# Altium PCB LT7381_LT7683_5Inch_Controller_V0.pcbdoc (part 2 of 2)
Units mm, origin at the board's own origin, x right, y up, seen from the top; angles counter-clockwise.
Board outline 60 x 56 mm, 2 copper layers (Top Layer, Bottom Layer); 80 components, 113 nets, 434 pads, 201 vias.
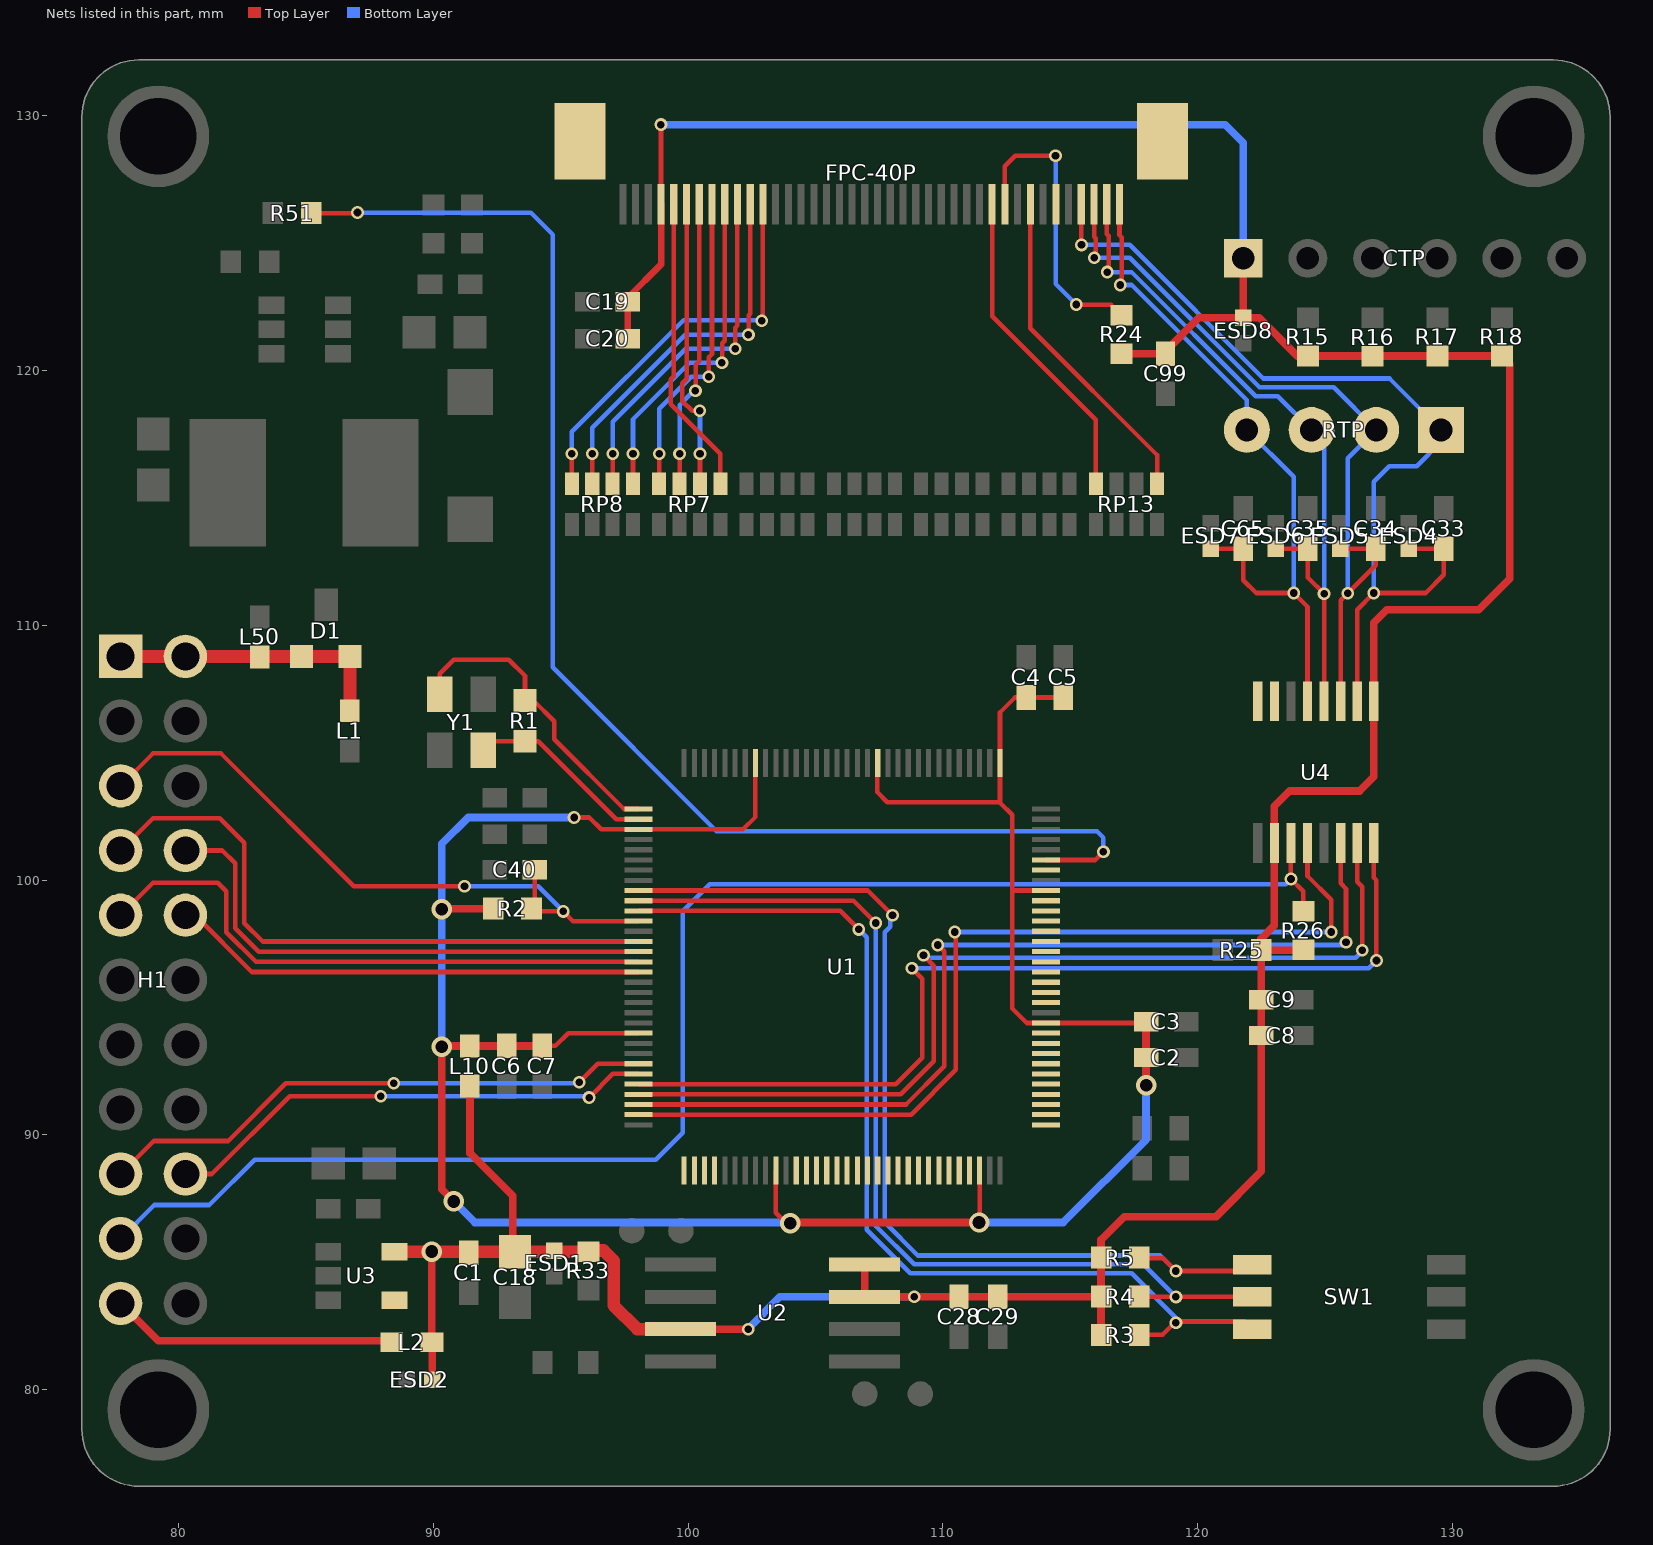
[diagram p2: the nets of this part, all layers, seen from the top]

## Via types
v1: diameter 0.5, hole 0.3, Top Layer to Bottom Layer, 104 vias
v2: diameter 0.8, hole 0.5, Top Layer to Bottom Layer, 97 vias

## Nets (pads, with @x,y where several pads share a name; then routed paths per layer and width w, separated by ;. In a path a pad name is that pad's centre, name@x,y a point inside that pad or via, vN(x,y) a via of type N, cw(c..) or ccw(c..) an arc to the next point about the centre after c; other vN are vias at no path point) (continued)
LT768_DB6_SDI: H1.17 U1.26 | length 22.1
  Top Layer w0.18: H1.17@77.724,88.46 79.02,89.756 81.941,89.756 84.204,92.019 88.441,92.019 v1(88.443,92.017) ; v1(95.725,92.056) 96.457,92.788 U1.26@98.045,92.788
  Bottom Layer w0.18: v1(88.443,92.017) 95.686,92.017 v1(95.725,92.056)
LT768_DB7_SCLK: H1.18 U1.27 | length 19.5
  Top Layer w0.18: H1.18@80.264,88.46 81.305,88.46 84.355,91.509 v1(87.935,91.509) ; v1(96.114,91.458) 97.043,92.388 U1.27@98.045,92.388
  Bottom Layer w0.18: v1(87.935,91.509) 87.937,91.507 96.065,91.507 v1(96.114,91.458)
LT768_INT: U1.36
LT768_PS0: R3.1 SW1.6 U1.11 | length 39.7
  Top Layer w0.18: U1.11@98.045,98.788 105.979,98.788 v1(106.705,98.061) ; R3.1@117.72,82.129 117.747,82.156 118.639,82.156 119.151,82.669 121.844,82.669 SW1.6@122.149,82.364 SW1.6@122.453,82.364
  Bottom Layer w0.18: v1(106.705,98.061) 107.01,97.756 107.01,86.276 108.727,84.559 117.414,84.559 119.151,82.821 v1(119.151,82.618)
LT768_PS1: R4.1 SW1.5 U1.10 | length 39
  Top Layer w0.18: U1.10@98.045,99.188 106.493,99.188 v1(107.366,98.315) ; R4.1@117.721,83.648 117.734,83.634 v1(119.151,83.634) SW1.5@122.149,83.634
  Bottom Layer w0.18: v1(107.366,98.315) 107.366,86.416 108.872,84.909 117.876,84.909 v1(119.151,83.634)
LT768_PS2: R5.1 SW1.4 U1.9 | length 40
  Top Layer w0.18: U1.9@98.045,99.588 107.058,99.588 v1(108.026,98.62) ; R5.1@117.72,85.177 117.741,85.156 118.645,85.156 v1(119.151,84.65) 122.301,84.65 SW1.4@122.555,84.904
  Bottom Layer w0.18: v1(108.026,98.62) 107.938,98.532 107.938,98.166 107.716,97.944 107.716,86.561 109.018,85.26 118.542,85.26 v1(119.151,84.65)
LT768_PWM0: U1.90
LT768_PWM1: R51.1 U1.91 | length 54.2
  Top Layer w0.18: R51.1@85.208,126.179 86.994,126.179 v1(87.02,126.206) ; U1.91@114.045,100.788 115.985,100.788 v1(116.307,101.109)
  Bottom Layer w0.18: v1(87.02,126.206) 93.828,126.206 94.691,125.342 94.691,108.348 101.117,101.922 116.053,101.922 116.307,101.668 v1(116.307,101.109)
LT768_RD#: H1.7 U1.14 | length 24.7
  Top Layer w0.18: H1.7@77.724,101.16 78.994,102.43 81.61,102.43 82.58,101.46 82.58,98.31 83.303,97.588 U1.14@98.045,97.588
LT768_RS/A0: H1.9 U1.16 | length 23.1
  Top Layer w0.18: H1.9@77.724,98.62 78.994,99.89 81.534,99.89 81.87,99.554 81.87,97.954 83.036,96.788 U1.16@98.045,96.788
LT768_RST: C40.1 H1.5 R2.1 U1.12 | length 26.5
  Top Layer w0.18: H1.5@77.724,103.7 78.994,104.97 81.661,104.97 86.875,99.756 v1(91.225,99.756) ; R2.1@93.853,98.874 R2.1@93.958,98.769 ; C40.1@93.98,100.398 93.98,98.791 R2.1@93.958,98.769 ; U1.12@98.045,98.388 95.482,98.388 v1(95.101,98.769) R2.1@93.958,98.769
  Bottom Layer w0.18: v1(91.225,99.756) 94.114,99.756 v1(95.101,98.769)
LT768_VDD3.3V: C2.1 C3.1 C4.1 C5.1 C6.1 C7.1 L10.2 R2.2 U1.3 U1.23 U1.42 U1.62 U1.75 U1.88 U1.97 U1.109 U1.121 | length 104.9
  Top Layer w0.18: C7.1@94.382,93.486 94.789,93.486 95.29,93.988 U1.23@98.045,93.988 ; v1(95.525,102.456) 96.125,102.456 96.593,101.988 U1.3@98.045,101.988 102.157,101.988 102.645,102.476 U1.121@102.645,104.588 ; U1.42@103.445,88.588 103.445,86.945 103.861,86.53 v2(104.013,86.53) ; U1.109@107.445,104.588 107.425,104.568 107.425,103.456 107.825,103.056 112.245,103.056 ; v2@111.445,86.576 U1.62@111.445,88.588 ; U1.88@114.045,99.588 112.73,99.588 112.725,99.583 ; C5.1@114.732,107.166 C4.1@113.278,107.166 112.835,107.166 112.245,106.576 U1.97@112.245,104.588 112.245,103.056 ; C3.1@117.981,94.428 117.94,94.388 U1.75@114.045,94.388 113.293,94.388 112.725,94.956 112.725,99.583 ; 112.245,103.056 112.245,103.036 112.725,102.556 112.725,99.583
  Top Layer w0.3: v2(90.325,98.856) 90.343,98.874 R2.2@92.346,98.874 ; v2@90.925,87.256 90.325,87.856 v2(90.325,93.456) 90.355,93.486 L10.2@91.423,93.486 C6.1@92.883,93.486 C7.1@94.28,93.486 ; v2(104.013,86.53) 104.039,86.556 v2(111.425,86.556) ; v2@117.981,91.956 C2.1@117.981,93.031 C3.1@117.981,94.428
  Bottom Layer w0.3: v2(90.325,93.456) v2(90.325,98.856) 90.325,101.418 91.363,102.456 v1(95.525,102.456) ; v2(90.799,87.382) 91.625,86.556 103.987,86.556 v2(104.013,86.53) ; v2(111.425,86.556) 114.725,86.556 117.981,89.812 v2@117.981,91.956
  other v2: 117.983,91.94
LT768_WAIT: H1.10 U1.17 | length 18.7
  Top Layer w0.18: H1.10@80.264,98.62 80.645,98.62 82.877,96.388 U1.17@98.045,96.388
LT768_WR#: H1.8 U1.15 | length 20.9
  Top Layer w0.18: H1.8@80.264,101.16 81.712,101.16 82.22,100.652 82.22,98.112 83.144,97.188 U1.15@98.045,97.188
LT768_XI: R1.1 U1.1 Y1.3 | length 12.2
  Top Layer w0.18: Y1.3@90.25,107.299 90.25,108.098 90.805,108.653 92.964,108.653 93.597,108.02 R1.1@93.597,107.049 93.933,107.049 94.742,106.24 94.742,105.53 97.484,102.788 U1.1@98.045,102.788
LT768_XO: R1.2 U1.2 Y1.1 | length 7.5
  Top Layer w0.18: Y1.1@91.95,105.099 92.3,105.449 R1.2@93.597,105.449 94.112,105.449 97.173,102.388 U1.2@98.045,102.388
ON/OFF: FPC-40P.31 R24.2 | length 11.2
  Top Layer w0.18: FPC-40P.31@112.438,126.528 112.438,128.026 112.852,128.44 v1(114.427,128.44) ; v1(115.24,122.598) 115.259,122.578 116.611,122.578
  Bottom Layer w0.18: v1(114.427,128.44) 114.427,123.41 v1(115.24,122.598)
PCLK: FPC-40P.30 RP13.8 | length 12.7
  Top Layer w0.18: FPC-40P.30@111.938,126.528 111.938,122.14 116.012,118.066 RP13.8@116.012,115.559
R0: FPC-40P.5 RP7.5 | length 11.8
  Top Layer w0.18: FPC-40P.5@99.438,126.528 99.438,119.777 99.325,119.663 99.325,118.676 101.267,116.734 RP7.5@101.267,115.559
R1: FPC-40P.6 RP7.6 | length 11.4
  Top Layer w0.18: FPC-40P.6@99.938,126.528 99.948,126.519 99.948,119.677 99.778,119.507 99.778,118.803 100.157,118.424 v1(100.457,118.424) ; RP7.6@100.467,115.559 v1@100.467,116.644
  Bottom Layer w0.18: v1(100.457,118.424) 100.467,118.414 v1(100.467,116.733)
  other v1: 100.467,116.733
R2: FPC-40P.7 RP7.7 | length 11.3
  Top Layer w0.18: RP7.7@99.667,115.559 v1(99.667,116.733) ; v1(100.288,119.208) 100.298,119.218 100.298,120.23 100.438,120.37 FPC-40P.7@100.438,126.528
  Bottom Layer w0.18: v1(99.667,116.733) 99.667,118.65 100.225,119.208 v1(100.288,119.208)
R3: FPC-40P.8 RP7.8 | length 12.2
  Top Layer w0.18: RP7.8@98.867,115.559 v1(98.867,116.733) ; v1(100.808,119.758) 100.818,119.768 100.818,120.519 100.938,120.639 FPC-40P.8@100.938,126.528
  Bottom Layer w0.18: v1(98.867,116.733) 98.867,118.508 100.117,119.758 v1(100.808,119.758)
R4: FPC-40P.9 RP8.5 | length 13.2
  Top Layer w0.18: RP8.5@97.838,115.559 v1(97.838,116.733) ; v1(101.328,120.308) 101.338,120.318 101.338,121.069 101.438,121.169 FPC-40P.9@101.438,126.528
  Bottom Layer w0.18: v1(97.838,116.733) 97.838,118.091 100.055,120.308 v1(101.328,120.308)
R5: FPC-40P.10 RP8.6 | length 14.1
  Top Layer w0.18: RP8.6@97.038,115.559 v1(97.038,116.733) ; v1(101.848,120.858) 101.858,120.868 101.858,121.689 101.938,121.769 FPC-40P.10@101.938,126.528
  Bottom Layer w0.18: v1(97.038,116.733) 97.038,117.986 99.91,120.858 v1(101.848,120.858)
R6: FPC-40P.11 RP8.7 | length 15
  Top Layer w0.18: RP8.7@96.238,115.559 v1(96.238,116.733) ; v1(102.368,121.408) 102.378,121.418 102.378,122.169 102.438,122.229 FPC-40P.11@102.438,126.528
  Bottom Layer w0.18: v1(96.238,116.733) 96.238,117.761 99.885,121.408 v1(102.368,121.408)
R7: FPC-40P.12 RP8.8 | length 15.9
  Top Layer w0.18: RP8.8@95.438,115.559 v1(95.438,116.733) ; v1(102.888,121.958) 102.938,122.008 FPC-40P.12@102.938,126.528
  Bottom Layer w0.18: v1(95.438,116.733) 95.438,117.596 99.822,121.98 102.866,121.98 v1(102.888,121.958)
RTP_CS: U1.29 U4.15 | length 38.2
  Top Layer w0.18: U1.29@98.045,91.588 108.357,91.588 109.652,92.883 109.652,96.639 v1(109.245,97.045) ; U4.15@126.269,101.458 126.269,99.935 126.467,99.738 v1(126.467,97.248)
  Bottom Layer w0.18: v1(109.245,97.045) 109.349,96.942 126.211,96.942 126.467,97.198 v1(126.467,97.248)
RTP_DCLK: U1.28 U4.16 | length 38.3
  Top Layer w0.18: U1.28@98.045,91.988 108.157,91.988 109.195,93.026 109.195,96.131 v1(108.788,96.537) ; U4.16@126.919,101.458 126.919,100.098 127.025,99.992 v1(127.025,96.842)
  Bottom Layer w0.18: v1(108.788,96.537) 108.991,96.537 108.993,96.535 126.719,96.535 v1(127.025,96.842)
RTP_DIN: U1.30 U4.14 | length 37.6
  Top Layer w0.18: U1.30@98.045,91.188 108.557,91.188 110.058,92.689 110.058,97.198 v1(109.804,97.452) ; U4.14@125.619,101.458 125.619,99.874 125.832,99.661 v1(125.832,97.554)
  Bottom Layer w0.18: v1(109.804,97.452) 109.806,97.45 125.727,97.45 v1(125.832,97.554)
RTP_INT: H1.19 R26.2 U4.11 | length 59.8
  Top Layer w0.18: U4.11@123.669,101.458 123.658,101.447 123.658,100.057 v1(123.673,100.042) 124.155,99.56 R26.2@124.155,98.769
  Bottom Layer w0.18: H1.19@77.724,85.92 79.045,87.241 81.204,87.241 82.983,89.02 98.731,89.02 99.797,90.086 99.797,98.772 100.858,99.834 123.464,99.834 v1(123.673,100.042)
RTP_SDO: U1.31 U4.12 | length 37.3
  Top Layer w0.18: U1.31@98.045,90.788 108.757,90.788 110.515,92.546 110.515,97.909 v1(110.465,97.96) ; U4.12@124.319,101.458 124.319,100.158 125.247,99.23 v1(125.247,97.96)
  Bottom Layer w0.18: v1(110.465,97.96) v1(125.247,97.96)
VDD_3.3V: C1.1 C8.1 C9.1 C18.1 C19.1 C20.1 C28.1 C29.1 C99.1 CTP.1 ESD1.1 ESD2.1 ESD8.1 FPC-40P.4 L2.1 L10.1 R3.2 R4.2 R5.2 R15.1 R16.1 R17.1 R18.1 R24.1 R25.2 R26.1 R33.2 U2.3 U2.7 U2.8 U3.5 U4.1 U4.10 | length 154.2
  Top Layer w0.18: v1(98.933,129.659) 98.938,129.653 FPC-40P.4@98.938,126.528 ; v1(102.357,82.369) v1@102.362,82.364 ; R26.1@124.138,97.245 R26.1@124.155,97.262
  Top Layer w0.2: L2.1@89.941,81.857 L2.1@89.951,81.848
  Top Layer w0.254: C20.1@97.625,121.251 C19.1@97.625,122.701 ; C19.1@97.627,122.701 97.627,122.858 98.938,124.169 FPC-40P.4@98.938,126.528
  Top Layer w0.3: L2.1@89.941,81.857 v2@89.941,85.41 ; ESD2.1@89.951,80.384 L2.1@89.951,81.848 ; L10.1@91.44,91.997 91.44,89.274 93.116,87.598 C18.1@93.116,85.41 ; 92.38,85.336 92.38,85.41 ; 92.55,85.41 92.804,85.41 C18.1@92.885,85.491 ; U2.3@99.707,82.369 v1(102.357,82.369) ; U2.8@106.93,84.909 U2.7@106.93,83.639 106.933,83.636 v1(108.882,83.636) C28.1@110.637,83.636 C29.1@112.161,83.636 116.203,83.636 R4.2@116.214,83.647 ; R3.2@116.214,82.129 R4.2@116.214,83.647 ; R24.1@117.018,120.665 118.74,120.665 C99.1@118.744,120.669 118.744,120.768 120.05,122.074 ESD8.1@121.793,122.074 ; CTP.1@121.793,124.401 ESD8.1@121.793,122.074 ; R26.1@124.138,97.245 R25.2@122.496,97.245 ; R4.2@116.214,83.648 R5.2@116.214,85.177 116.214,85.878 117.119,86.784 120.726,86.784 122.504,88.562 C8.1@122.504,93.896 C9.1@122.504,95.293 122.504,97.236 R25.2@122.496,97.245 ; ESD8.1@121.793,122.074 122.419,122.074 123.918,120.574 R15.1@124.333,120.574 R17.1@129.413,120.574 R18.1@131.953,120.574 132.258,120.269 132.258,111.828 131.039,110.609 127.432,110.609 126.919,110.096 U4.1@126.919,107.018 126.924,107.014 126.924,104.056 126.365,103.497 123.622,103.497 123.019,102.894 U4.10@123.019,101.458 123.019,98.217 122.496,97.693 R25.2@122.496,97.245
  Top Layer w0.5: U3.5@88.475,85.41 89.941,85.41 92.38,85.41 92.55,85.41 ; C18.1@92.804,85.41 93.116,85.41 95.988,85.41 96.034,85.456 96.68,85.456 97.079,85.058 97.079,83.302 98.012,82.369 U2.3@99.707,82.369
  Bottom Layer w0.3: v1(98.933,129.659) 121.082,129.659 121.793,128.948 CTP.1@121.793,124.401 ; v1(102.357,82.369) 102.357,82.385 103.607,83.634 108.88,83.634 v1(108.882,83.636)
  other v2: 89.941,85.412
VDD_3.3V_O: H1.21 L2.2 | length 11.3
  Top Layer w0.3: H1.21@77.724,83.38 79.196,81.908 88.316,81.908 L2.2@88.367,81.857
VIN: D1.1 D1.2 H1.1 H1.2 L1.1 L50.1 | length 11.1
  Top Layer w0.5: H1.1@77.724,108.78 H1.2@80.264,108.78 84.826,108.78 D1.2@86.73,108.78 ; L1.1@86.716,106.648 86.731,106.663 D1.2@86.731,108.779
VSYNC: FPC-40P.33 RP13.5 | length 13
  Top Layer w0.18: FPC-40P.33@113.438,126.528 113.438,121.66 118.412,116.686 RP13.5@118.412,115.559
X+: C33.1 ESD4.1 FPC-40P.37 RTP.1 U4.2 | length 36.8
  Top Layer w0.18: FPC-40P.37@115.438,126.528 115.438,124.939 v1(115.443,124.934) ; U4.2@126.269,107.018 126.269,110.615 v1(126.924,111.269) 128.956,111.269 129.667,111.98 129.667,113.009 C33.1@129.67,113.012 ESD4.1@128.295,113.012
  Bottom Layer w0.18: v1(115.443,124.934) 115.445,124.936 117.335,124.936 122.579,119.692 127.537,119.692 RTP.1@129.558,117.67 129.558,117.206 128.6,116.248 127.533,116.248 126.924,115.638 v1(126.924,111.269)
X-: C35.1 ESD6.1 FPC-40P.39 RTP.3 U4.4 | length 27.5
  Top Layer w0.18: FPC-40P.39@116.438,126.528 116.438,125.361 116.51,125.29 116.51,123.918 v1(116.459,123.868) ; ESD6.1@123.065,113.012 C35.1@124.336,113.012 124.333,113.009 124.333,111.879 v1(124.969,111.242) U4.4@124.969,107.018
  Bottom Layer w0.18: v1(116.459,123.868) 116.461,123.87 117.41,123.87 122.289,118.991 123.158,118.991 RTP.3@124.478,117.67 124.969,117.179 v1(124.969,111.242)
Y+: C34.1 ESD5.1 FPC-40P.38 RTP.2 U4.3 | length 30.9
  Top Layer w0.18: FPC-40P.38@115.938,126.528 115.938,125.252 116.002,125.188 116.002,124.477 v1(115.951,124.426) ; ESD5.1@125.605,113.012 C34.1@127.003,113.012 127.003,112.364 v1(125.902,111.263) 125.619,110.981 U4.3@125.619,107.018
  Bottom Layer w0.18: v1(115.951,124.426) 115.953,124.428 117.347,124.428 122.434,119.341 125.347,119.341 RTP.2@127.018,117.67 125.902,116.554 v1(125.902,111.263)
Y-: C65.1 ESD7.1 FPC-40P.40 RTP.4 U4.5 | length 27.6
  Top Layer w0.18: FPC-40P.40@116.938,126.528 116.938,125.319 117.018,125.239 117.018,123.41 v1(116.967,123.36) ; ESD7.1@120.525,113.012 C65.1@121.796,113.012 121.796,112.426 121.793,112.424 121.793,111.777 122.301,111.269 v1(123.774,111.269) 124.319,110.724 U4.5@124.319,107.018
  Bottom Layer w0.18: v1(116.967,123.36) 117.424,123.36 121.938,118.846 RTP.4@121.938,117.67 123.774,115.834 v1(123.774,111.269)
"": FPC-40P.35 FPC-40P.41 FPC-40P.42 U1.33 U1.34 U1.35 U1.44 U1.45 U1.46 U1.47 U1.48 U1.49 U1.50 U1.51 U1.52 U1.53 U1.54 U1.55 U1.56 U1.57 U1.58 U1.59 U1.60 U1.61 U1.65 U1.66 U1.67 U1.68 U1.69 U1.70 U1.71 U1.72 U1.73 U1.74 U1.77 U1.78 U1.79 U1.80 U1.81 U1.82 U1.83 U1.84 U1.85 U1.86 U1.87 U3.4 U4.7 U4.8

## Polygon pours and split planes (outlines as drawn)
GND on Bottom Layer (solid, remove dead copper, pour order 0): 76.2,76.2 76.2,111.982 92.507,111.982 93.777,113.252 93.777,132.2 136.2,132.2 136.2,76.2
GND on Bottom Layer (solid, remove dead copper, pour order 1): 76.2,112.286 92.354,112.286 93.472,113.404 93.472,132.2 76.2,132.2
GND on Top Layer (solid, remove dead copper, pour order 2): 76.2,76.2 76.2,111.982 92.507,111.982 93.777,113.252 93.777,132.2 136.2,132.2 136.2,76.2
GND on Top Layer (solid, remove dead copper, pour order 3): 76.2,112.286 92.354,112.286 93.472,113.404 93.472,132.2 76.2,132.2

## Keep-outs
Board Outline Layer:
  the board outline again, w0.254

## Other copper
Top Layer:
  drawing of 449 lines, arcs and shapes, not listed
Bottom Layer:
  region net Y-: 122.171,116.801 122.766,116.716 122.893,116.843 122.808,117.437
  region net Y-: 122.388,118.45 122.028,118.846 121.848,118.846 121.488,118.45
  region net X-: 124.526,116.772 124.879,116.428 125.059,116.545 125.281,117.263
  region net X-: 124.245,118.54 123.651,118.625 123.524,118.498 123.609,117.903
  region net Y+: 126.149,117.437 126.064,116.843 126.191,116.716 126.785,116.801
  region net Y+: 126.785,118.54 126.191,118.625 126.064,118.498 126.149,117.903
  region net X+: 128.563,118.539 128.658,118.252 128.976,118.57 128.69,118.666
  region net X+: 128.9,116.675 129.155,116.675 129.441,116.77 128.805,116.77
  region net RTP_INT: 78.545,86.14 78.629,86.698 78.502,86.825 77.944,86.741
  region net CTP_INT: 81.104,85.792 81.354,86.4 81.283,86.583 80.795,86.584
  region net FLASH_SPI_SO: 101.817,83.509 101.95,83.544 101.95,83.724 101.817,83.759
  region net FLASH_SPI_SCLK: 103.976,82.239 104.109,82.274 104.109,82.454 103.976,82.489
  region net FLASH_SPI_SCLK: 104.812,82.489 104.679,82.454 104.679,82.274 104.812,82.239
  region net FLASH_SPI_SO: 103.137,84.331 103.067,84.212 103.194,84.085 103.313,84.155
  region net LT768_RST: 95.036,99.01 94.917,99.08 94.79,98.953 94.86,98.834
  region net LT768_RST: 91.442,99.631 91.575,99.666 91.575,99.846 91.442,99.881
  region net R6: 96.363,116.95 96.328,117.083 96.148,117.083 96.113,116.95
  region net R5: 97.163,116.95 97.128,117.083 96.948,117.083 96.913,116.95
  region net R4: 97.963,116.95 97.928,117.083 97.748,117.083 97.713,116.95
  region net R3: 98.992,116.95 98.957,117.083 98.777,117.083 98.742,116.95
  region net R2: 99.792,116.95 99.757,117.083 99.577,117.083 99.542,116.95
  region net R7: 95.563,116.95 95.528,117.083 95.348,117.083 95.313,116.95
  region net R7: 102.684,122.102 102.547,122.07 102.531,121.89 102.662,121.853
  region net R6: 102.152,121.533 102.018,121.498 102.018,121.318 102.152,121.283
  region net R5: 101.632,120.983 101.498,120.948 101.498,120.768 101.632,120.733
  region net R4: 101.112,120.433 100.978,120.398 100.978,120.218 101.112,120.183
  region net R3: 100.592,119.883 100.458,119.848 100.458,119.668 100.592,119.633
  region net R2: 100.039,119.188 99.959,119.069 100.063,118.919 100.181,118.982
  region net R1: 100.592,116.95 100.557,117.083 100.377,117.083 100.342,116.95
  region net R1: 100.592,116.95 100.557,117.083 100.377,117.083 100.342,116.95
  region net R1: 100.341,118.203 100.377,118.071 100.557,118.078 100.59,118.213
  region net G7: 102.421,116.95 102.386,117.083 102.206,117.083 102.171,116.95
  region net G6: 103.221,116.95 103.186,117.083 103.006,117.083 102.971,116.95
  region net G5: 104.021,116.95 103.986,117.083 103.806,117.083 103.771,116.95
  region net G4: 104.821,116.95 104.786,117.083 104.606,117.083 104.571,116.95
  region net G3: 105.85,116.95 105.815,117.083 105.635,117.083 105.6,116.95
  region net G2: 106.65,116.95 106.615,117.083 106.435,117.083 106.4,116.95
  region net G1: 107.45,116.95 107.415,117.083 107.235,117.083 107.2,116.95
  region net G7: 106.7,122.065 106.569,122.028 106.582,121.848 106.718,121.816
  region net G6: 106.431,121.582 106.281,121.571 106.201,121.391 106.33,121.353
  region net G5: 105.746,121.081 105.613,121.046 105.613,120.866 105.746,120.831
  region net G4: 105.175,120.362 105.087,120.245 105.177,120.08 105.295,120.143
  region net G3: 105.6,119.339 105.635,119.206 105.815,119.206 105.85,119.339
  region net G2: 106.4,118.839 106.435,118.706 106.615,118.706 106.65,118.839
  region net G1: 107.2,118.339 107.235,118.206 107.415,118.206 107.45,118.339
  region net B7: 109.279,116.95 109.244,117.083 109.064,117.083 109.029,116.95
  region net B6: 110.079,116.95 110.044,117.083 109.864,117.083 109.829,116.95
  region net B5: 110.879,116.95 110.844,117.083 110.664,117.083 110.629,116.95
  region net B4: 111.679,116.95 111.644,117.083 111.464,117.083 111.429,116.95
  region net B3: 112.708,116.95 112.673,117.083 112.493,117.083 112.458,116.95
  region net B2: 113.508,116.95 113.473,117.083 113.293,117.083 113.258,116.95
  region net B1: 114.308,116.95 114.273,117.083 114.093,117.083 114.058,116.95
  region net B7: 110.709,122.081 110.575,122.046 110.575,121.866 110.709,121.831
  region net B6: 110.384,120.991 110.314,120.872 110.441,120.745 110.56,120.815
  region net B5: 110.884,120.491 110.814,120.372 110.941,120.245 111.06,120.315
  region net B4: 111.444,119.884 111.464,119.739 111.644,119.685 111.683,119.813
  region net B3: 112.453,119.26 112.493,119.132 112.673,119.177 112.696,119.32
  region net B2: 113.255,118.693 113.293,118.564 113.473,118.641 113.484,118.792
  region net B1: 114.06,118.133 114.093,117.995 114.273,118.113 114.269,118.27
  region net DE: 117.003,117.232 116.981,117.376 116.801,117.425 116.761,117.298
  region net DE: 116.766,118.775 116.801,118.642 116.981,118.642 117.016,118.775
  region net LT768_PS2: 119.087,84.891 118.968,84.961 118.84,84.834 118.91,84.715
  region net LT768_PS1: 119.087,83.875 118.968,83.945 118.84,83.818 118.91,83.699
  region net LT768_PS0: 119.237,82.853 119.13,82.97 118.914,82.932 118.991,82.81
  region net LT768_DB7_SCLK: 95.926,91.623 95.784,91.597 95.749,91.417 95.877,91.378
  region net LT768_DB6_SDI: 95.492,92.146 95.363,92.107 95.391,91.927 95.531,91.899
  region net LT768_DB5_SDO: 95.384,92.691 95.361,92.62 95.489,92.492 95.56,92.514
  region net LT768_DB5_SDO: 88.142,92.431 88.275,92.466 88.275,92.646 88.142,92.681
  region net LT768_DB6_SDI: 88.659,91.892 88.793,91.927 88.793,92.107 88.659,92.142
  region net LT768_DB7_SCLK: 88.15,91.382 88.284,91.417 88.286,91.597 88.152,91.632
  region net LT768_VDD3.3V: 90.525,93.802 90.475,94.016 90.175,94.016 90.125,93.802
  region net LT768_VDD3.3V: 90.525,99.202 90.475,99.416 90.175,99.416 90.125,99.202
  region net LT768_VDD3.3V: 90.125,98.51 90.175,98.296 90.475,98.296 90.525,98.51
  region net LT768_VDD3.3V: 90.903,86.996 91.089,86.88 91.301,87.092 91.185,87.278
  region net LT768_VDD3.3V: 111.771,86.356 111.985,86.406 111.985,86.706 111.771,86.756
  region net LT768_VDD3.3V: 117.781,91.595 117.831,91.381 118.131,91.379 118.181,91.592
  region net LT768_VDD3.3V: 103.681,86.752 103.463,86.706 103.444,86.406 103.654,86.353
  region net RTP_SDO: 110.681,97.835 110.815,97.87 110.815,98.05 110.681,98.085
  region net RTP_DIN: 110.02,97.325 110.153,97.36 110.155,97.54 110.022,97.575
  region net RTP_CS: 109.391,96.842 109.542,96.852 109.624,97.032 109.494,97.069
  region net RTP_DCLK: 109.004,96.41 109.137,96.445 109.139,96.625 109.006,96.66
  region net Y-: 123.899,111.486 123.864,111.619 123.684,111.619 123.649,111.486
  region net X-: 125.094,111.459 125.059,111.592 124.879,111.592 124.844,111.459
  region net Y+: 126.027,111.48 125.992,111.613 125.812,111.613 125.777,111.48
  region net X+: 127.049,111.486 127.014,111.619 126.834,111.619 126.799,111.486
  region net CTP_SDA: 99.882,106.873 100.01,106.912 99.972,107.092 99.831,107.118
  region net LT768_PWM1: 116.432,101.326 116.397,101.459 116.217,101.459 116.182,101.326
  region net LT768_PS2: 107.833,98.461 107.848,98.313 108.028,98.245 108.067,98.373
  region net LT768_PS0: 106.77,97.82 106.889,97.75 107.017,97.877 106.947,97.997
  region net ON/OFF: 114.302,128.223 114.337,128.09 114.517,128.09 114.552,128.223
  region net ON/OFF: 115.175,122.839 115.056,122.909 114.929,122.781 114.998,122.662
  region net RTP_SDO: 125.031,98.085 124.897,98.05 124.897,97.87 125.031,97.835
  region net RTP_DIN: 125.583,97.577 125.453,97.54 125.536,97.36 125.687,97.35
  region net RTP_CS: 126.237,97.15 126.173,97.031 126.318,96.922 126.437,97
  region net RTP_DCLK: 126.784,96.777 126.714,96.658 126.842,96.531 126.961,96.601
  region net LT768_PWM1: 87.237,126.081 87.37,126.116 87.37,126.296 87.237,126.331
  region net X-: 116.676,123.744 116.81,123.78 116.808,123.96 116.674,123.994
  region net Y-: 117.184,123.235 117.317,123.27 117.317,123.45 117.184,123.485
  region net RTP_INT: 123.431,99.978 123.401,99.898 123.528,99.77 123.608,99.801
  region net CTP_RST: 111.138,98.749 111.272,98.784 111.272,98.964 111.138,98.999
  region net CTP_SCL: 123.813,109.215 123.946,109.25 123.946,109.43 123.813,109.465
  region net CTP_SDA: 128.892,107.127 128.758,107.092 128.758,106.912 128.892,106.877
  region net CTP_SDA: 132.244,107.243 132.125,107.313 131.997,107.186 132.067,107.067
  region net CTP_SCL: 130.39,109.465 130.257,109.43 130.257,109.25 130.39,109.215

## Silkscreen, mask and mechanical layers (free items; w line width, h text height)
Top Silkscreen Layer:
  lines w0.1 net "": 121.945,87.884 131.267,87.884 131.267,92.202 121.945,92.202 121.945,87.884
  text "8080" at 123.723,91.051 h1
  text "6800" at 126.263,91.051 h1
  text "4-SPI" at 128.753,91.051 h1
  text "PS2" at 122.199,90.035 h1
  text "0" at 124.333,90.035 h1
  text "0" at 126.873,90.035 h1
  text "1" at 129.565,90.035 h1
  text "PS1" at 122.199,88.968 h1
  text "0" at 124.333,88.968 h1
  text "1" at 126.873,88.968 h1
  text "0" at 129.565,88.968 h1
  text "X" at 124.282,87.952 h1
  text "X" at 126.822,87.952 h1
  text "1" at 129.565,87.952 h1
  text "PS0" at 122.199,87.901 h1
Bottom Silkscreen Layer:
  lines w0.2 net "": 88.129,81.908 88.138,81.917 88.138,110.254 ; 81.788,81.875 94.779,81.875 94.779,110.28 81.788,110.28 81.788,81.875 ; 120.498,119.398 135.763,119.398 135.763,122.928 120.498,122.928 120.498,119.398 ; 120.688,113.012 130.828,113.012 130.828,116.096 120.688,116.096 120.688,113.012
  text "LT7381/LT7683_5Inch_Controller V1.0" at 120.57,129.244 h2.15
  text "Levetop Semiconductor." at 120.5,126.432 h2.15
  text "INT" at 123.318,120.525 h0.84 r270
  text "SCL" at 130.968,120.045 h0.84 r270
  text "RST" at 125.868,120.01 h0.84 r270
  text "GND" at 133.519,119.972 h0.84 r270
  text "3V3" at 120.768,119.936 h0.84 r270
  text "SDA" at 128.418,119.936 h0.84 r270
  text "X-" at 125.242,114.16 h0.84
  text "X+" at 130.322,114.16 h0.84
  text "Y-" at 122.738,114.124 h0.84
  text "Y+" at 127.818,114.124 h0.84
  text "+5V" at 86.034,108.308 h0.84
  text "+5V" at 92.701,108.308 h0.84
  text "GND" at 85.943,105.866 h0.84
  text "GND" at 92.61,105.866 h0.84
  text "RST" at 85.987,103.336 h0.84
  text "CS#" at 92.564,103.336 h0.84
  text "RD#" at 86.006,100.69 h0.84
  text "WR#" at 92.657,100.69 h0.84
  text "RS" at 85.554,97.925 h0.84
  text "WAIT" at 92.85,97.925 h0.84
  text "DB0" at 85.923,95.439 h0.84
  text "DB1" at 92.426,95.439 h0.84
  text "DB2" at 85.923,92.953 h0.84
  text "DB3" at 92.591,92.953 h0.84
  text "DB4/SCS" at 87.513,90.579 h0.84
  text "DB5/SDO" at 94.18,90.579 h0.84
  text "DB6/SDI" at 87.199,87.988 h0.84
  text "DB7/SCK" at 94.162,87.988 h0.84
  text "RTP-INT" at 87.218,85.495 h0.84
  text "CTP-INT" at 93.903,85.495 h0.84
  text "3V3" at 85.96,83.009 h0.84
  text "GND" at 92.61,83.009 h0.84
